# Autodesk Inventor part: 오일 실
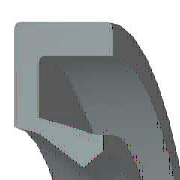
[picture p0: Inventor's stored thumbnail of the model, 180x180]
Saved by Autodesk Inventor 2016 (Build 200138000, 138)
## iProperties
IsCustomPart: 1
Created: 2012-02
Part Number: 오일 실
Material: 고무
Description: 오일 실 - 스프링 장착, 비스프링, 고무 덮개 G
Document SubType Name: Modeling
Standard: JIS B 2402
Designer: mduedu
Standards Organization: JIS
Language: ko-KR
Size Designation: 20 32 5 A
Categories: <MemberInstance><Categories><Category DisplayName="샤프트 부품" InternalName="7f7aeb1f-a693-4053-b835-cee3144e0d98" Mnemonic="SHFT"><Category DisplayName="실링" Intern
Density: 0.93 g/cm^3
Appearance: 고무 - 검은색 - 버전 1.1
Mass: 1.24044 g
Surface Area: 19.8228 cm^2
Volume: 1.33381 cm^3
Author: mduedu
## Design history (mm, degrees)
body "Solid1"
revolve "회전1" stored, may be unused: angle "d29" = 360 deg
chamfer "모따기1" distance "d30" = 0.25 (= 0.05 x b); stored, may be unused: second distance "d31" = 0.5 (= 0.1 x b), angle "d39" = 45 deg
chamfer "모따기2" distance "d32" = 0.5 (= 0.1 x b); stored, may be unused: second distance "d33" = 0.25 (= 0.05 x b), angle "d40" = 45 deg
fillet "모깎기1" dims "d34" = 0.25 (= 0.05 x b)
sketch "스케치2"
  geometry: L1 (10.997, -3.438)-(11.297, -5); L2 (10.597, -3.282)-(10.997, -3.438); L3 (10, -1.72)-(10.597, -3.282); L4 (11.091, -1.22)-(10, -1.72); L5 (12.133, -3.75)-(11.091, -1.22); L6 (13.333, -3.75)-(12.133, -3.75); L7 (14.667, -1.25)-(13.333, -3.75); L8 (14.667, 0)-(14.667, -1.25); L9 (16, 0)-(14.667, 0); L10 (16, -5)-(16, 0); L11 (11.297, -5)-(16, -5); L12 (0, -9.6)-(0, 1.6) reference; L13 (28, 0)-(14, 0) reference
  constraints: 22 end point, 3 horizontal, 2 vertical
  dimensions: "d2" = 5 distance of L10.start L9.start (= b); "d4" = 1.25 vertical distance of L5.start L1.end (= 0.25 x b); "d6" = 1.33333 distance of L9.start L8.start (= 0.111111 x dd - 0.111111 x Diam); "d8" = 1.25 distance of L8.start L7.start (= 0.25 x b); "d10" = 1.33333 horizontal distance of L7.start L6.start (= 0.111111 x dd - 0.111111 x Diam); "d12" = 1.21951 vertical distance of L9.start L4.start (= 0.243902 x b); "d14" = 1.09091 horizontal distance of L4.start L3.start (= 0.0909091 x dd - 0.0909091 x Diam); "d16" = 0.5 vertical distance of L4.start L3.start (= 0.1 x b); "d18" = 1.2 distance of L6.start L5.start (= 0.1 x dd - 0.1 x Diam); "d20" = 1.5625 vertical distance of L3.start L2.start (= 0.3125 x b); "d22" = 0.59701 horizontal distance of L3.start L2.start (= 0.0497512 x dd - 0.0497512 x Diam); "d24" = 0.3 horizontal distance of L1.start L1.end (= 0.025 x dd - 0.025 x Diam); "d26" = 1.5625 vertical distance of L1.start L1.end (= 0.3125 x b); "d28" = 0.4 horizontal distance of L2.start L1.start (= 0.0333333 x dd - 0.0333333 x Diam); "d35" = 0 distance between parallel lines of L13 L9; "d36" = 16 distance between parallel lines of L12 L10 (= 0.5 x dd); "d37" = 10 distance from line of L12 L3.start (= 0.5 x Diam)
other parameters: "dd" = 32 [user parameter; used in 8 equation terms], "b" = 5 [user parameter; used in 12 equation terms], "d1" = 8 (derived), "d3" = 2 (derived), "d5" = 2.22222 (derived), "d7" = 2 (derived), "d9" = 2.22222 (derived), "d11" = 1.95122 (derived), "d13" = 1.81818 (derived), "d15" = 0.8 (derived), "d17" = 2 (derived), "d19" = 2.5 (derived), "d21" = 0.99502 (derived), "d23" = 0.5 (derived), "d25" = 2.5 (derived), "d27" = 0.66667 (derived), "d38" = 0
